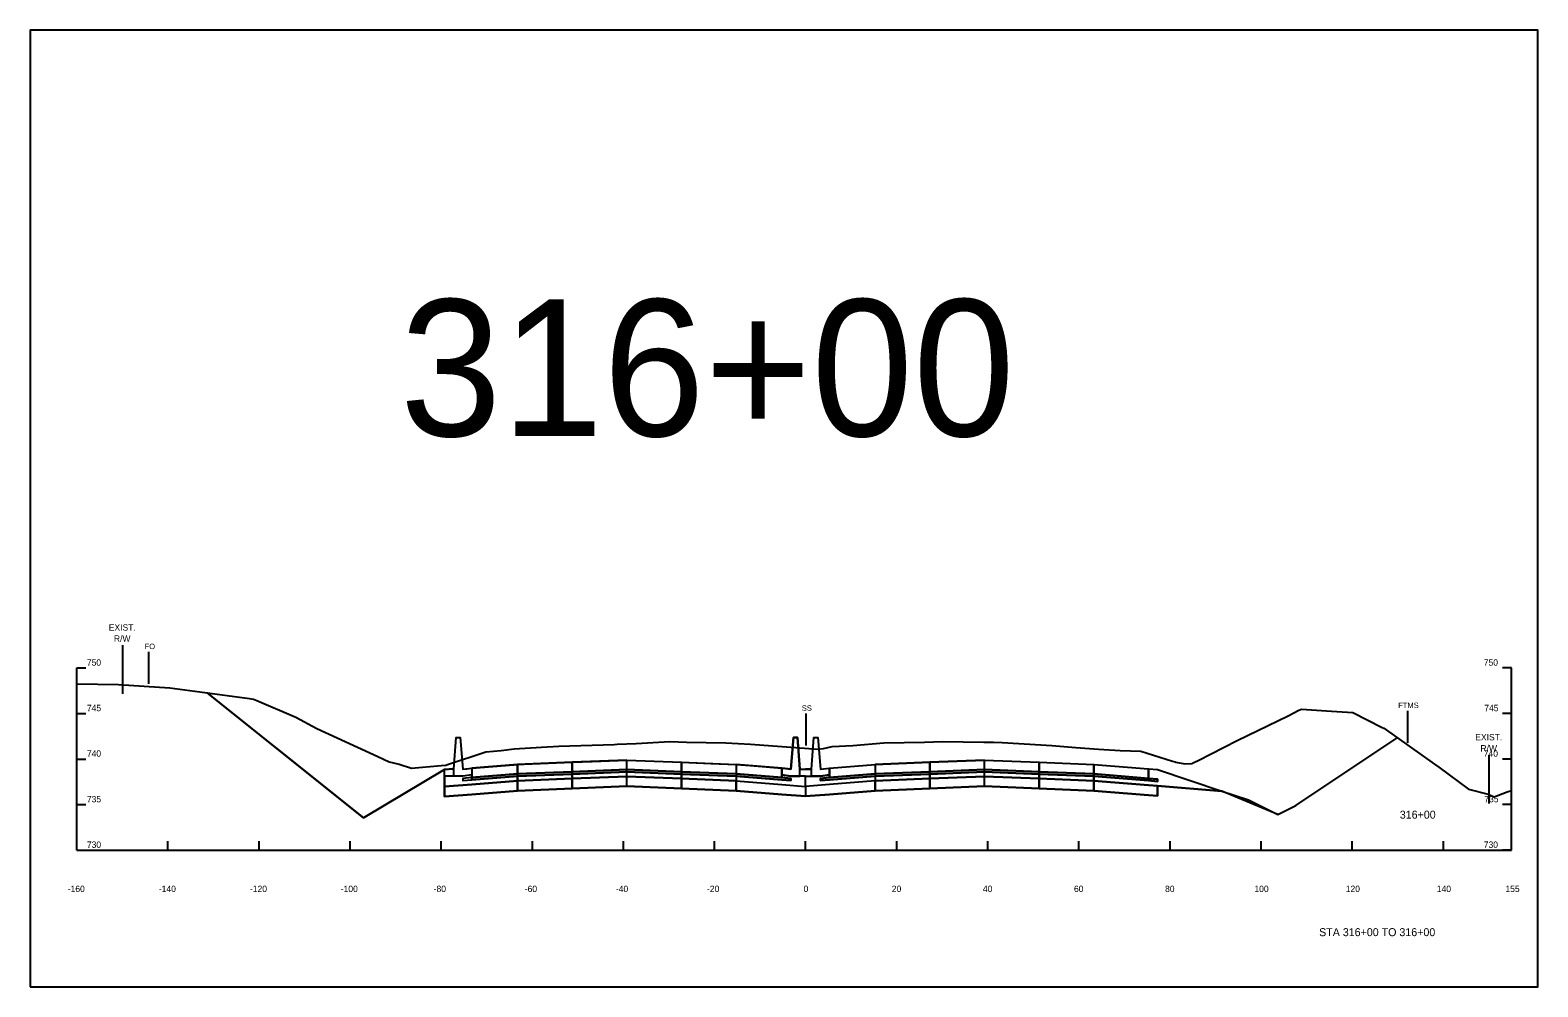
# Model space of a CAD drawing. Extents: x 0 to 2149228, y 0 to 2148913.
# Drawn here: x 2146922.7 to 2147253.7, y 2146662.7 to 2146872.7 of the extents above; entities that cross this region are included whole.
import ezdxf

# ---------------------------------------------------------------- set-up
doc = ezdxf.new("R2010")
doc.units = 0
for name, color, linetype in [('ADAMS CONST', 7, 'Continuous'), ('Default', 7, 'Continuous'), ('P_E_XS_Ground', 7, 'Continuous'), ('P_E_XS_RW', 7, 'Continuous'), ('P_E_XS_UTL', 7, 'Continuous'), ('P_MISC_TXT', 7, 'Continuous'), ('P_PROF_Grades', 7, 'Continuous'), ('P_RDWY_BarrierConc', 7, 'Continuous'), ('P_XS', 7, 'Continuous'), ('P_XS_Subgrade', 7, 'Continuous')]:
    doc.layers.add(name, color=color, linetype=linetype)

msp = doc.modelspace()

# ---------------------------------------------------------------- linework, layer by layer
at = {"layer": 'Default'}
msp.add_lwpolyline([(2146922.75, 2146662.69), (2147253.75, 2146662.69), (2147253.75, 2146872.69), (2146922.75, 2146872.69)], close=True, dxfattribs=at)
at = {"layer": 'P_E_XS_Ground'}
msp.add_lwpolyline([(2146933, 2146729.23), (2146942.12, 2146729.05), (2146953.42, 2146728.33), (2146960.03, 2146727.43), (2146970.89, 2146725.99), (2146971.76, 2146725.86), (2146972.49, 2146725.51), (2146981.05, 2146721.86), (2146985.67, 2146719.36), (2146999.08, 2146713.25), (2147001.54, 2146712.05), (2147003.77, 2146711.57), (2147006.48, 2146710.68), (2147013.01, 2146711.27), (2147014.01, 2146711.38), (2147014.36, 2146711.51), (2147022.77, 2146714.24), (2147026.14, 2146714.6), (2147028.99, 2146714.94), (2147035.04, 2146715.3), (2147038.78, 2146715.52), (2147050.96, 2146715.91), (2147051.61, 2146715.95), (2147055.8, 2146716.12), (2147063.18, 2146716.51), (2147066.87, 2146716.38), (2147075.49, 2146716.22), (2147080.91, 2146715.95), (2147095.68, 2146714.88), (2147096.91, 2146714.98), (2147098.86, 2146715.42), (2147103.33, 2146715.64), (2147110.17, 2146716.22), (2147119.07, 2146716.39), (2147123.06, 2146716.54), (2147132.09, 2146716.41), (2147134.27, 2146716.38), (2147136.18, 2146716.29), (2147147.04, 2146715.68), (2147152.3, 2146715.23), (2147157.27, 2146714.88), (2147162.06, 2146714.6), (2147166.57, 2146714.39), (2147173.57, 2146712.23), (2147174.1, 2146712.05), (2147174.29, 2146712.02), (2147176.25, 2146711.64), (2147177.79, 2146711.7), (2147178.37, 2146711.97), (2147179.18, 2146712.4), (2147187.76, 2146716.73), (2147198.95, 2146722.19), (2147201.29, 2146723.39), (2147201.89, 2146723.65), (2147208.46, 2146723.23), (2147213.11, 2146722.93), (2147219.56, 2146719.64), (2147219.92, 2146719.45), (2147231.09, 2146711.53), (2147232.04, 2146710.92), (2147238.54, 2146706.05), (2147242.85, 2146704.97), (2147244.17, 2146704.39), (2147247.01, 2146705.49), (2147248, 2146705.81)], dxfattribs=at)
at = {"layer": 'P_E_XS_RW'}
for p, q in [((2146943, 2146737.66), (2146943, 2146727)), ((2147243, 2146713.57), (2147243, 2146702.91))]:
    msp.add_line(p, q, dxfattribs=at)
at = {"layer": 'P_E_XS_UTL'}
for p, q in [((2146948.8, 2146729.22), (2146948.8, 2146736.22)), ((2147093.09, 2146715.67), (2147093.09, 2146722.67)), ((2147225.23, 2146716.28), (2147225.23, 2146723.28))]:
    msp.add_line(p, q, dxfattribs=at)
at = {"layer": 'P_RDWY_BarrierConc'}
for p, q in [((2146933, 2146692.69), (2146933, 2146732.69)), ((2146933, 2146732.69), (2146935, 2146732.69)), ((2147248, 2146732.69), (2147246, 2146732.69)), ((2147248, 2146692.69), (2147248, 2146732.69)), ((2146933, 2146722.69), (2146935, 2146722.69)), ((2147248, 2146722.69), (2147246, 2146722.69)), ((2146933, 2146712.69), (2146935, 2146712.69)), ((2147248, 2146712.69), (2147246, 2146712.69)), ((2146933, 2146702.69), (2146935, 2146702.69)), ((2147248, 2146702.69), (2147246, 2146702.69)), ((2146933, 2146692.69), (2146933, 2146694.69)), ((2146953, 2146692.69), (2146953, 2146694.69)), ((2146973, 2146692.69), (2146973, 2146694.69)), ((2146993, 2146692.69), (2146993, 2146694.69)), ((2147013, 2146692.69), (2147013, 2146694.69)), ((2147033, 2146692.69), (2147033, 2146694.69)), ((2147053, 2146692.69), (2147053, 2146694.69)), ((2147073, 2146692.69), (2147073, 2146694.69)), ((2147093, 2146692.69), (2147093, 2146694.69)), ((2147113, 2146692.69), (2147113, 2146694.69)), ((2147133, 2146692.69), (2147133, 2146694.69)), ((2147153, 2146692.69), (2147153, 2146694.69)), ((2147173, 2146692.69), (2147173, 2146694.69)), ((2147193, 2146692.69), (2147193, 2146694.69)), ((2147213, 2146692.69), (2147213, 2146694.69)), ((2147233, 2146692.69), (2147233, 2146694.69)), ((2147248, 2146692.69), (2147248, 2146694.69)), ((2146933, 2146692.69), (2146935, 2146692.69)), ((2146933, 2146692.69), (2147248, 2146692.69)), ((2147248, 2146692.69), (2147246, 2146692.69))]:
    msp.add_line(p, q, dxfattribs=at)
at = {"layer": 'P_XS'}
for points in [[(2146961.6, 2146727.23), (2146976.58, 2146715.24), (2146995.92, 2146699.76), (2147013.75, 2146710.37), (2147015.51, 2146710.51), (2147015.75, 2146710.53), (2147016.31, 2146717.44), (2147017.19, 2146717.44), (2147017.75, 2146710.44), (2147018.65, 2146710.55), (2147019.75, 2146710.69), (2147028.94, 2146711.43), (2147029.75, 2146711.49), (2147031.21, 2146711.55), (2147041.75, 2146711.97), (2147046.12, 2146712.15), (2147053.75, 2146712.45), (2147065.75, 2146711.97), (2147072.16, 2146711.72), (2147077.75, 2146711.49), (2147080.85, 2146711.24), (2147087.75, 2146710.69), (2147088.61, 2146710.58), (2147089.75, 2146710.44), (2147090.31, 2146717.44), (2147091.19, 2146717.44), (2147091.75, 2146710.44), (2147093, 2146710.44)], [(2147093, 2146710.44), (2147094.25, 2146710.44), (2147094.81, 2146717.44), (2147095.69, 2146717.44), (2147096.25, 2146710.44), (2147098.25, 2146710.69), (2147108.25, 2146711.49), (2147120.25, 2146711.97), (2147132.25, 2146712.45), (2147144.25, 2146711.97), (2147156.25, 2146711.49), (2147168.25, 2146710.53), (2147170.25, 2146710.37), (2147184.39, 2146705.66), (2147190.25, 2146703.7), (2147196.64, 2146700.51), (2147200.64, 2146702.51), (2147222.89, 2146717.34)], [(2147015.75, 2146710.53), (2147013.75, 2146710.37)], [(2147093, 2146710.44), (2147094.25, 2146710.44), (2147093, 2146710.44)]]:
    msp.add_lwpolyline(points, dxfattribs=at)
for points in [[(2147015.75, 2146710.53), (2147016.31, 2146717.44), (2147017.19, 2146717.44), (2147017.75, 2146710.44), (2147019.75, 2146710.69), (2147019.75, 2146709.19), (2147017.75, 2146708.94), (2147015.75, 2146708.94)], [(2147091.75, 2146710.44), (2147091.19, 2146717.44), (2147090.31, 2146717.44), (2147089.75, 2146710.44), (2147087.75, 2146710.69), (2147087.75, 2146709.19), (2147089.75, 2146708.94), (2147091.75, 2146708.94)], [(2147094.25, 2146710.44), (2147094.81, 2146717.44), (2147095.69, 2146717.44), (2147096.25, 2146710.44), (2147098.25, 2146710.69), (2147098.25, 2146709.19), (2147096.25, 2146708.94), (2147094.25, 2146708.94)], [(2147029.75, 2146711.49), (2147019.75, 2146710.69), (2147019.75, 2146708.61), (2147029.75, 2146709.41)], [(2147041.75, 2146711.97), (2147029.75, 2146711.49), (2147029.75, 2146709.41), (2147041.75, 2146709.89)], [(2147029.75, 2146711.49), (2147029.75, 2146711.49), (2147029.75, 2146709.41), (2147029.75, 2146709.41)], [(2147053.75, 2146712.45), (2147041.75, 2146711.97), (2147041.75, 2146709.89), (2147053.75, 2146710.37)], [(2147053.75, 2146712.45), (2147065.75, 2146711.97), (2147065.75, 2146709.89), (2147053.75, 2146710.37)], [(2147065.75, 2146711.97), (2147077.75, 2146711.49), (2147077.75, 2146709.41), (2147065.75, 2146709.89)], [(2147087.75, 2146708.61), (2147087.75, 2146710.69), (2147077.75, 2146711.49), (2147077.75, 2146709.41)], [(2147098.25, 2146708.61), (2147098.25, 2146710.69), (2147108.25, 2146711.49), (2147108.25, 2146709.41)], [(2147120.25, 2146711.97), (2147108.25, 2146711.49), (2147108.25, 2146709.41), (2147120.25, 2146709.89)], [(2147132.25, 2146712.45), (2147120.25, 2146711.97), (2147120.25, 2146709.89), (2147132.25, 2146710.37)], [(2147132.25, 2146712.45), (2147144.25, 2146711.97), (2147144.25, 2146709.89), (2147132.25, 2146710.37)], [(2147144.25, 2146711.97), (2147156.25, 2146711.49), (2147156.25, 2146709.41), (2147144.25, 2146709.89)], [(2147156.25, 2146711.49), (2147156.25, 2146711.49), (2147156.25, 2146709.41), (2147156.25, 2146709.41)], [(2147156.25, 2146711.49), (2147168.25, 2146710.53), (2147168.25, 2146708.45), (2147156.25, 2146709.41)], [(2147156.25, 2146708.91), (2147168.25, 2146707.95), (2147170.25, 2146707.79), (2147170.25, 2146708.29), (2147168.25, 2146708.45), (2147168.25, 2146710.53), (2147170.25, 2146710.37), (2147184.39, 2146705.66), (2147170.25, 2146706.79), (2147168.25, 2146706.95), (2147156.25, 2146707.91)], [(2147029.75, 2146708.91), (2147019.75, 2146708.11), (2147019.75, 2146708.61), (2147019.75, 2146709.19), (2147017.75, 2146708.94), (2147013.75, 2146708.94), (2147013.75, 2146706.63), (2147019.75, 2146707.11), (2147029.75, 2146707.91)], [(2147029.75, 2146707.91), (2147019.75, 2146707.11), (2147013.75, 2146706.63), (2147013.75, 2146704.46), (2147019.75, 2146704.94), (2147029.75, 2146705.74)], [(2147019.75, 2146708.61), (2147017.75, 2146708.45), (2147017.75, 2146707.95), (2147019.75, 2146708.11)], [(2147029.75, 2146709.41), (2147019.75, 2146708.61), (2147019.75, 2146708.11), (2147029.75, 2146708.91)], [(2147041.75, 2146709.89), (2147029.75, 2146709.41), (2147029.75, 2146708.91), (2147041.75, 2146709.39)], [(2147029.75, 2146709.41), (2147029.75, 2146709.41), (2147029.75, 2146708.91), (2147029.75, 2146708.91)], [(2147041.75, 2146709.39), (2147029.75, 2146708.91), (2147029.75, 2146707.91), (2147041.75, 2146708.39)], [(2147029.75, 2146708.91), (2147029.75, 2146708.91), (2147029.75, 2146707.91), (2147029.75, 2146707.91)], [(2147041.75, 2146708.39), (2147029.75, 2146707.91), (2147029.75, 2146705.74), (2147041.75, 2146706.22)], [(2147029.75, 2146707.91), (2147029.75, 2146707.91), (2147029.75, 2146705.74), (2147029.75, 2146705.74)], [(2147053.75, 2146710.37), (2147041.75, 2146709.89), (2147041.75, 2146709.39), (2147053.75, 2146709.87)], [(2147053.75, 2146709.87), (2147041.75, 2146709.39), (2147041.75, 2146708.39), (2147053.75, 2146708.87)], [(2147053.75, 2146708.87), (2147041.75, 2146708.39), (2147041.75, 2146706.22), (2147053.75, 2146706.7)], [(2147053.75, 2146710.37), (2147065.75, 2146709.89), (2147065.75, 2146709.39), (2147053.75, 2146709.87)], [(2147053.75, 2146709.87), (2147065.75, 2146709.39), (2147065.75, 2146708.39), (2147053.75, 2146708.87)], [(2147053.75, 2146708.87), (2147065.75, 2146708.39), (2147065.75, 2146706.22), (2147053.75, 2146706.7)], [(2147065.75, 2146709.89), (2147077.75, 2146709.41), (2147077.75, 2146708.91), (2147065.75, 2146709.39)], [(2147065.75, 2146709.39), (2147077.75, 2146708.91), (2147077.75, 2146707.91), (2147065.75, 2146708.39)], [(2147077.75, 2146705.74), (2147065.75, 2146706.22), (2147065.75, 2146708.39), (2147077.75, 2146707.91)], [(2147087.75, 2146708.11), (2147089.75, 2146707.95), (2147089.75, 2146708.45), (2147087.75, 2146708.61), (2147077.75, 2146709.41), (2147077.75, 2146708.91)], [(2147087.75, 2146708.11), (2147077.75, 2146708.91), (2147077.75, 2146707.91), (2147087.75, 2146707.11), (2147093, 2146706.69), (2147093, 2146708.94), (2147089.75, 2146708.94), (2147087.75, 2146709.19), (2147087.75, 2146708.61), (2147089.75, 2146708.45), (2147089.75, 2146707.95)], [(2147077.75, 2146707.91), (2147087.75, 2146707.11), (2147093, 2146706.69), (2147093, 2146704.52), (2147087.75, 2146704.94), (2147077.75, 2146705.74)], [(2147098.25, 2146708.11), (2147108.25, 2146708.91), (2147108.25, 2146707.91), (2147098.25, 2146707.11), (2147093, 2146706.69), (2147093, 2146708.94), (2147096.25, 2146708.94), (2147098.25, 2146709.19), (2147098.25, 2146708.61), (2147096.25, 2146708.45), (2147096.25, 2146707.95)], [(2147108.25, 2146707.91), (2147098.25, 2146707.11), (2147093, 2146706.69), (2147093, 2146704.52), (2147098.25, 2146704.94), (2147108.25, 2146705.74)], [(2147098.25, 2146708.11), (2147096.25, 2146707.95), (2147096.25, 2146708.45), (2147098.25, 2146708.61), (2147108.25, 2146709.41), (2147108.25, 2146708.91)], [(2147120.25, 2146709.89), (2147108.25, 2146709.41), (2147108.25, 2146708.91), (2147120.25, 2146709.39)], [(2147120.25, 2146709.39), (2147108.25, 2146708.91), (2147108.25, 2146707.91), (2147120.25, 2146708.39)], [(2147120.25, 2146708.39), (2147108.25, 2146707.91), (2147108.25, 2146705.74), (2147120.25, 2146706.22)], [(2147132.25, 2146710.37), (2147120.25, 2146709.89), (2147120.25, 2146709.39), (2147132.25, 2146709.87)], [(2147132.25, 2146709.87), (2147120.25, 2146709.39), (2147120.25, 2146708.39), (2147132.25, 2146708.87)], [(2147132.25, 2146708.87), (2147120.25, 2146708.39), (2147120.25, 2146706.22), (2147132.25, 2146706.7)], [(2147132.25, 2146710.37), (2147144.25, 2146709.89), (2147144.25, 2146709.39), (2147132.25, 2146709.87)], [(2147132.25, 2146709.87), (2147144.25, 2146709.39), (2147144.25, 2146708.39), (2147132.25, 2146708.87)], [(2147132.25, 2146708.87), (2147144.25, 2146708.39), (2147144.25, 2146706.22), (2147132.25, 2146706.7)], [(2147144.25, 2146709.89), (2147156.25, 2146709.41), (2147156.25, 2146708.91), (2147144.25, 2146709.39)], [(2147144.25, 2146709.39), (2147156.25, 2146708.91), (2147156.25, 2146707.91), (2147144.25, 2146708.39)], [(2147144.25, 2146708.39), (2147156.25, 2146707.91), (2147156.25, 2146705.74), (2147144.25, 2146706.22)], [(2147156.25, 2146709.41), (2147156.25, 2146709.41), (2147156.25, 2146708.91), (2147156.25, 2146708.91)], [(2147156.25, 2146709.41), (2147168.25, 2146708.45), (2147170.25, 2146708.29), (2147170.25, 2146707.79), (2147168.25, 2146707.95), (2147156.25, 2146708.91)], [(2147156.25, 2146708.91), (2147156.25, 2146708.91), (2147156.25, 2146707.91), (2147156.25, 2146707.91)], [(2147156.25, 2146707.91), (2147156.25, 2146707.91), (2147156.25, 2146705.74), (2147156.25, 2146705.74)], [(2147156.25, 2146707.91), (2147168.25, 2146706.95), (2147170.25, 2146706.79), (2147170.25, 2146704.62), (2147168.25, 2146704.78), (2147156.25, 2146705.74)]]:
    msp.add_lwpolyline(points, close=True, dxfattribs=at)
at = {"layer": 'P_XS_Subgrade'}
for points in [[(2146995.92, 2146699.76), (2146961.6, 2146727.23)], [(2147200.64, 2146702.51), (2147222.89, 2146717.34)], [(2147013.75, 2146710.37), (2146995.92, 2146699.76)], [(2147029.75, 2146705.74), (2147029.75, 2146705.74), (2147019.75, 2146704.94), (2147013.75, 2146704.46), (2147013.75, 2146708.94), (2147013.75, 2146710.37)], [(2147041.75, 2146706.22), (2147029.75, 2146705.74), (2147029.75, 2146705.74)], [(2147053.75, 2146706.7), (2147041.75, 2146706.22)], [(2147053.75, 2146706.7), (2147065.75, 2146706.22), (2147053.75, 2146706.7)], [(2147065.75, 2146706.22), (2147077.75, 2146705.74), (2147065.75, 2146706.22)], [(2147120.25, 2146706.22), (2147108.25, 2146705.74), (2147120.25, 2146706.22)], [(2147132.25, 2146706.7), (2147120.25, 2146706.22), (2147132.25, 2146706.7)], [(2147132.25, 2146706.7), (2147144.25, 2146706.22)], [(2147144.25, 2146706.22), (2147156.25, 2146705.74), (2147144.25, 2146706.22)], [(2147156.25, 2146705.74), (2147156.25, 2146705.74), (2147168.25, 2146704.78), (2147170.25, 2146704.62), (2147170.25, 2146706.79), (2147184.39, 2146705.66)], [(2147196.64, 2146700.51), (2147184.39, 2146705.66), (2147190.25, 2146703.7)], [(2147196.64, 2146700.51), (2147200.64, 2146702.51)]]:
    msp.add_lwpolyline(points, dxfattribs=at)
for points in [[(2147077.75, 2146705.74), (2147087.75, 2146704.94), (2147093, 2146704.52), (2147087.75, 2146704.94)], [(2147098.25, 2146704.94), (2147108.25, 2146705.74), (2147098.25, 2146704.94), (2147093, 2146704.52)]]:
    msp.add_lwpolyline(points, close=True, dxfattribs=at)

# ---------------------------------------------------------------- texts
at = {"layer": 'ADAMS CONST'}
msp.add_text('316+00', height=30, dxfattribs=at).set_placement((2147003.92, 2146783.57))
at = {"layer": 'Default'}
for p in [(2146961.56, 2146727.18), (2147222.86, 2146717.29), (2147013.72, 2146704.41), (2147029.72, 2146705.69), (2147053.72, 2146706.65), (2147077.72, 2146705.69), (2147092.97, 2146704.47), (2147092.97, 2146704.47), (2147098.22, 2146704.89), (2147108.22, 2146705.69), (2147132.22, 2146706.65), (2147156.22, 2146705.69), (2147170.22, 2146704.57), (2147184.36, 2146705.61), (2147190.22, 2146703.65), (2147196.61, 2146700.46), (2147200.61, 2146702.46), (2146995.89, 2146699.71)]:
    msp.add_text('+', height=0.1, dxfattribs=at).set_placement(p)
at = {"layer": 'P_E_XS_RW'}
for s, p in [('EXIST.', (2146940.01, 2146740.88)), ('R/W', (2146941.14, 2146738.43)), ('EXIST.', (2147240.01, 2146716.79)), ('R/W', (2147241.14, 2146714.34))]:
    msp.add_text(s, height=1.4, rotation=360, dxfattribs=at).set_placement(p)
at = {"layer": 'P_E_XS_UTL'}
for s, p in [('FO', (2146947.87, 2146736.82)), ('SS', (2147092.16, 2146723.27)), ('FTMS', (2147223.09, 2146723.88))]:
    msp.add_text(s, height=1.2, rotation=360, dxfattribs=at).set_placement(p)
at = {"layer": 'P_MISC_TXT'}
for s, p in [('316+00', (2147223.44, 2146699.61)), ('STA 316+00 TO 316+00', (2147205.73, 2146673.81))]:
    msp.add_text(s, height=1.75, dxfattribs=at).set_placement(p)
at = {"layer": 'P_PROF_Grades'}
for s, p in [('750', (2146935.2, 2146733.19)), ('750', (2147241.87, 2146733.19)), ('745', (2146935.2, 2146723.19)), ('745', (2147241.99, 2146723.19)), ('740', (2146935.2, 2146713.19)), ('740', (2147241.87, 2146713.19)), ('735', (2146935.2, 2146703.19)), ('735', (2147241.99, 2146703.19)), ('730', (2146935.2, 2146693.19)), ('730', (2147241.87, 2146693.19)), ('-160', (2146931, 2146683.49)), ('-140', (2146951, 2146683.49)), ('-120', (2146971, 2146683.49)), ('-100', (2146990.94, 2146683.49)), ('-80', (2147011.34, 2146683.49)), ('-60', (2147031.34, 2146683.49)), ('-40', (2147051.34, 2146683.49)), ('-20', (2147071.34, 2146683.49)), ('0', (2147092.54, 2146683.49)), ('20', (2147111.91, 2146683.49)), ('40', (2147131.91, 2146683.49)), ('60', (2147151.91, 2146683.49)), ('80', (2147171.91, 2146683.49)), ('100', (2147191.52, 2146683.49)), ('120', (2147211.57, 2146683.49)), ('140', (2147231.57, 2146683.49)), ('155', (2147246.63, 2146683.49))]:
    msp.add_text(s, height=1.4, dxfattribs=at).set_placement(p)
at = {"layer": 'P_RDWY_BarrierConc'}
msp.add_text('-', height=0.0001, dxfattribs=at).set_placement((2146933, 2146692.69))

doc.saveas('drawing.dxf')
